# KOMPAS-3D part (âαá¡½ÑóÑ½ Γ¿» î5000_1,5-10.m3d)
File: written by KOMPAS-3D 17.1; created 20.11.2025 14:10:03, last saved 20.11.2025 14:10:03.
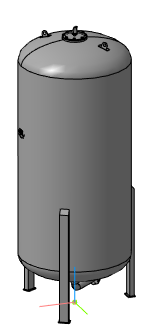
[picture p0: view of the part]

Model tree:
1. Операция без истории:1

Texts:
  REVIT MATERIAL OVERRIDDEN
  REVIT MATERIAL ID
  REVIT SUBCATEGORY ID
  REVIT CATEGORY ID
  REVIT ELEMENT ID
  REVIT BREP TAG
